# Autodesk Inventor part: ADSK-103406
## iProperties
Shininess: 0.0
Created: 2000-09
Part Number: ADSK-103406
Document SubType Name: Modeling
Stock Number: ADSK-103406
Density: 1 g/cm^3
Density: 0.0
Volumn: 0.0
Area: 0.0
PropertySet Name: Model Information
Control State: 0
Master: False
Checked Out: False
Author: gao
